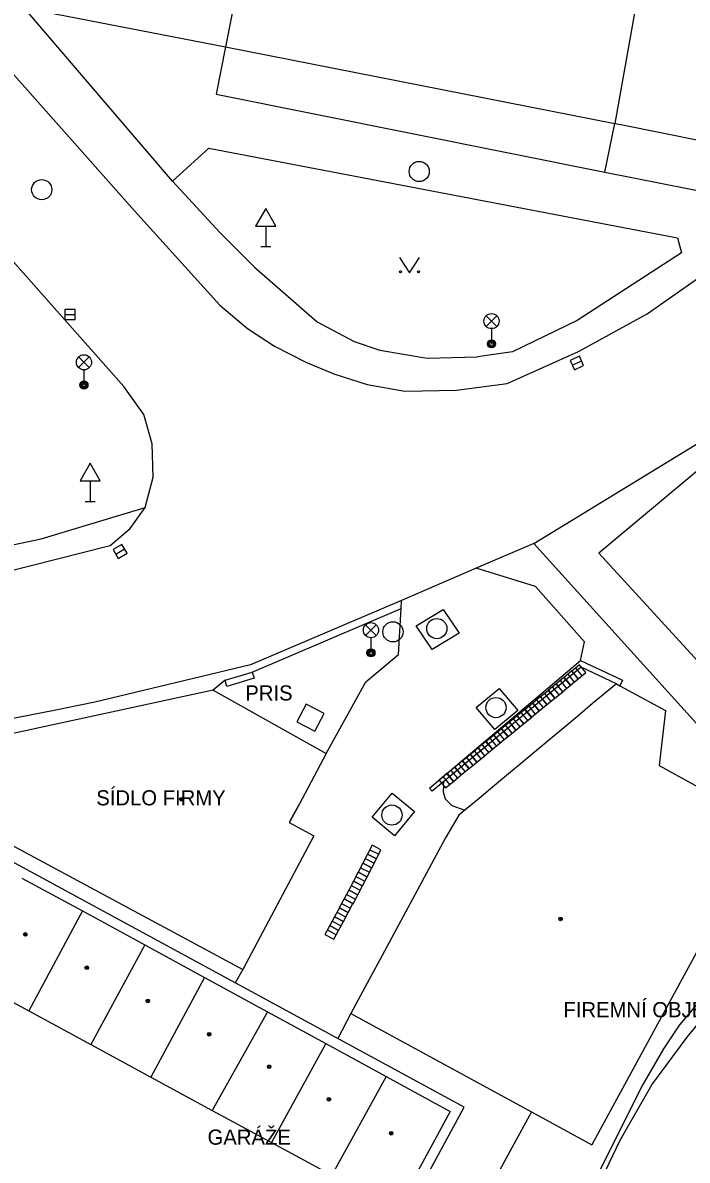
# Model space of a CAD drawing. Extents: x -598233 to -596890, y -1157848 to -1156431.
# Drawn here: x -597063.7 to -597030.8, y -1157692.2 to -1157635.8 of the extents above; entities that cross this region are included whole.
import ezdxf

# ---------------------------------------------------------------- set-up
doc = ezdxf.new("R2010")
doc.units = 0
for name, color, linetype in [('Level 10', 7, 'Continuous'), ('Level 11', 7, 'Continuous'), ('Level 14', 7, 'Continuous'), ('Level 24', 7, 'Continuous'), ('Level 26', 7, 'Continuous'), ('Level 27', 7, 'Continuous'), ('Level 33', 7, 'Continuous'), ('Level 34', 7, 'Continuous'), ('Level 36', 7, 'Continuous'), ('Level 39', 7, 'Continuous'), ('Level 41', 7, 'Continuous'), ('Level 5', 7, 'Continuous'), ('Level 6', 7, 'Continuous'), ('Level 7', 7, 'Continuous')]:
    doc.layers.add(name, color=color, linetype=linetype)

msp = doc.modelspace()

# ---------------------------------------------------------------- linework, layer by layer
at = {"layer": 'Level 10'}
for points in [[(-597149.32, -1157542.42), (-597114.43, -1157581.74), (-597058.19, -1157645.1599), (-597053.96, -1157649.83)], [(-597044.81, -1157654.08), (-597042.24, -1157654.04), (-597039.73, -1157653.71), (-597036.2, -1157652.12), (-597032.81, -1157650.25), (-597030.26, -1157648.4699), (-596998.03, -1157621.12)], [(-597076.44, -1157633.83), (-597058.71, -1157653.85)], [(-597053.96, -1157649.83), (-597052.6, -1157650.98), (-597051.25, -1157651.86), (-597049.71, -1157652.65), (-597048.31, -1157653.23), (-597046.67, -1157653.75), (-597044.81, -1157654.08)], [(-597057.6599, -1157659.84), (-597057.27, -1157658.34), (-597057.32, -1157656.69), (-597057.7199, -1157655.24), (-597058.71, -1157653.85)], [(-597038.4099, -1157661.63), (-597029.25, -1157656.04)], [(-597075.37, -1157664.84), (-597070.49, -1157664.28), (-597067.29, -1157663.73), (-597059.39, -1157661.7199), (-597058.4099, -1157660.89), (-597057.6599, -1157659.84)], [(-597038.41, -1157661.63), (-597041.27, -1157662.85), (-597044.97, -1157664.44), (-597052.45, -1157667.64)], [(-597052.45, -1157667.64), (-597060.15, -1157669.48), (-597062.1599, -1157669.89), (-597066.94, -1157670.81)], [(-597034.14, -1157691.17), (-597032.58, -1157688.43), (-597030.83, -1157686.06), (-597028.79, -1157683.59), (-597026.04, -1157680.94)], [(-597050.02, -1157722.18), (-597035.59, -1157694.21), (-597034.14, -1157691.17)]]:
    msp.add_lwpolyline(points, dxfattribs=at)
at = {"layer": 'Level 11'}
for points in [[(-597063.65, -1157635.1), (-597053.68, -1157637.04)], [(-597056.3, -1157643.68), (-597063.65, -1157635.1)], [(-597053.68, -1157637.04), (-597054.14, -1157639.38), (-597034.9, -1157643.25)], [(-597034.4099, -1157640.83), (-597034.11, -1157640.89), (-597028.05, -1157642.1), (-597022.5, -1157637.28), (-597021.17, -1157638.83)], [(-597034.9, -1157643.25), (-597034.4099, -1157640.83)], [(-597056.3, -1157643.68), (-597054.51, -1157642.06), (-597031.31, -1157646.49), (-597031.11, -1157647.23)], [(-597053.95, -1157646.25), (-597056.3, -1157643.68)], [(-597034.9, -1157643.25), (-597027.89, -1157644.63)], [(-597052.25, -1157647.95), (-597053.95, -1157646.25)], [(-597031.11, -1157647.23), (-597036.27, -1157650.58), (-597039.4699, -1157652.13), (-597041.2, -1157652.38)], [(-597052.25, -1157647.95), (-597049.15, -1157650.65), (-597047.31, -1157651.62), (-597046.04, -1157652.05), (-597043.7, -1157652.45), (-597041.2, -1157652.38)], [(-597029.25, -1157656.04), (-597028.77, -1157656.74), (-597035.2, -1157662.1), (-597021.37, -1157677.18)], [(-597097.96, -1157662.31), (-597091.6599, -1157662.87), (-597088.64, -1157663.06), (-597079.29, -1157663.24), (-597070.69, -1157662.87), (-597068.32, -1157662.55), (-597062.8, -1157661.39), (-597057.6599, -1157659.84)], [(-597036.1, -1157667.42), (-597035.91, -1157666.49), (-597038.33, -1157663.75), (-597041.27, -1157662.85)], [(-597048.7, -1157672.03), (-597046.74, -1157668.47), (-597045.12, -1157667.12), (-597044.99, -1157664.85), (-597044.97, -1157664.44)], [(-597052.36, -1157668), (-597044.99, -1157664.85)], [(-597044.24, -1157665.71), (-597042.9099, -1157664.89), (-597042.12, -1157666.06), (-597043.45, -1157666.88), (-597044.24, -1157665.71)], [(-597043.58, -1157673.74), (-597036.1, -1157667.42)], [(-597036.1, -1157667.42), (-597034.03, -1157668.39)], [(-597036.08, -1157667.75), (-597042.88, -1157673.41), (-597043.45, -1157673.89)], [(-597034.33, -1157668.57), (-597036.08, -1157667.75)], [(-597053.7, -1157668.4), (-597054.29, -1157668.89)], [(-597034.03, -1157668.39), (-597034.15, -1157668.67)], [(-597041.27, -1157669.74), (-597040.13, -1157668.8), (-597039.2, -1157669.89), (-597040.35, -1157670.83), (-597041.27, -1157669.74)], [(-597042.89, -1157673.59), (-597042.9099, -1157673.92)], [(-597042.89, -1157673.59), (-597042.88, -1157673.41)], [(-597045.43, -1157673.98), (-597044.33, -1157674.9), (-597045.31, -1157676.1), (-597046.42, -1157675.18), (-597045.43, -1157673.98)], [(-597043.45, -1157673.89), (-597043.58, -1157673.74)], [(-597042.9099, -1157673.92), (-597042.8, -1157674.27)], [(-597051.69, -1157707.64), (-597041.87, -1157689.53), (-597069.6599, -1157674.45), (-597072.96, -1157680.5), (-597074.59, -1157679.61), (-597075.37, -1157681.09)], [(-597042.8, -1157674.27), (-597042.4699, -1157674.59)], [(-597042.4699, -1157674.59), (-597041.83, -1157674.83)], [(-597052.82, -1157682.72), (-597053.21, -1157683.38)], [(-597047.47, -1157684.89), (-597048.12, -1157686.14)], [(-597031.2, -1157685.46), (-597032, -1157686.64), (-597033.02, -1157688.41), (-597034.54, -1157691.43), (-597038.61, -1157699.61), (-597038.62, -1157699.63), (-597044.68, -1157711.84)]]:
    msp.add_lwpolyline(points, dxfattribs=at)
at = {"layer": 'Level 14'}
for points in [[(-597030.3, -1157684.38), (-597031.2, -1157685.46)], [(-597038.53, -1157689.77), (-597043.51, -1157698.89)]]:
    msp.add_lwpolyline(points, dxfattribs=at)
at = {"layer": 'Level 24'}
msp.add_lwpolyline([(-597053.7, -1157668.4), (-597052.36, -1157668), (-597052.27, -1157668.3), (-597053.61, -1157668.7), (-597053.7, -1157668.4)], dxfattribs=at)
at = {"layer": 'Level 26'}
msp.add_lwpolyline([(-597050.1449, -1157670.4607), (-597049.2592, -1157670.925), (-597048.7949, -1157670.0393), (-597049.6806, -1157669.575)], close=True, dxfattribs=at)
at = {"layer": 'Level 27'}
for p, q in [((-597061.63, -1157650.29), (-597061.13, -1157650.29)), ((-597036.5079, -1157652.7928), (-597036.0521, -1157652.5872)), ((-597059.1159, -1157662.146), (-597058.6841, -1157661.894)), ((-597036.3484, -1157667.7866), (-597036.0316, -1157668.1734)), ((-597037.1184, -1157668.4166), (-597036.8016, -1157668.8034)), ((-597036.7284, -1157668.0966), (-597036.4116, -1157668.4834)), ((-597037.8884, -1157669.0566), (-597037.5716, -1157669.4434)), ((-597037.4984, -1157668.7366), (-597037.1816, -1157669.1234)), ((-597038.6584, -1157669.6866), (-597038.3416, -1157670.0734)), ((-597038.2784, -1157669.3666), (-597037.9616, -1157669.7534)), ((-597039.0484, -1157670.0066), (-597038.7316, -1157670.3934)), ((-597039.8183, -1157670.6366), (-597039.5015, -1157671.0234)), ((-597039.4284, -1157670.3166), (-597039.1116, -1157670.7034)), ((-597040.5884, -1157671.2666), (-597040.2716, -1157671.6534)), ((-597040.2084, -1157670.9566), (-597039.8916, -1157671.3434)), ((-597041.3584, -1157671.9066), (-597041.0416, -1157672.2934)), ((-597040.9784, -1157671.5866), (-597040.6616, -1157671.9734)), ((-597041.7484, -1157672.2266), (-597041.4316, -1157672.6134)), ((-597042.5184, -1157672.8566), (-597042.2016, -1157673.2434)), ((-597042.1384, -1157672.5366), (-597041.8216, -1157672.9234)), ((-597042.9084, -1157673.1766), (-597042.5916, -1157673.5634)), ((-597046.5423, -1157676.7856), (-597046.0977, -1157677.0144)), ((-597046.7723, -1157677.2256), (-597046.3277, -1157677.4544)), ((-597047.2321, -1157678.1152), (-597046.7879, -1157678.3448)), ((-597047.0023, -1157677.6756), (-597046.5577, -1157677.9044)), ((-597047.4613, -1157678.5637), (-597047.0187, -1157678.7963)), ((-597047.691, -1157679.0034), (-597047.2488, -1157679.2366)), ((-597047.9306, -1157679.4424), (-597047.4894, -1157679.6776)), ((-597048.3999, -1157680.3211), (-597047.9601, -1157680.5589)), ((-597048.1602, -1157679.8817), (-597047.7198, -1157680.1183)), ((-597048.6389, -1157680.7592), (-597048.2011, -1157681.0008))]:
    msp.add_line(p, q, dxfattribs=at)
for points in [[(-597061.63, -1157650.54), (-597061.13, -1157650.54), (-597061.13, -1157650.04), (-597061.63, -1157650.04)], [(-597036.4051, -1157653.0207), (-597035.9493, -1157652.8151), (-597036.1549, -1157652.3593), (-597036.6107, -1157652.5649)], [(-597058.9899, -1157662.3619), (-597058.5581, -1157662.1099), (-597058.8101, -1157661.6781), (-597059.2419, -1157661.9301)], [(-597036.9218, -1157668.2551), (-597036.6049, -1157668.6418), (-597036.2182, -1157668.3249), (-597036.5351, -1157667.9382)], [(-597036.5418, -1157667.9451), (-597036.2249, -1157668.3318), (-597035.8382, -1157668.0149), (-597036.1551, -1157667.6282)], [(-597037.6918, -1157668.8951), (-597037.3749, -1157669.2818), (-597036.9882, -1157668.9649), (-597037.3051, -1157668.5782)], [(-597037.3118, -1157668.5751), (-597036.9949, -1157668.9618), (-597036.6082, -1157668.6449), (-597036.9251, -1157668.2582)], [(-597038.0818, -1157669.2151), (-597037.7649, -1157669.6018), (-597037.3782, -1157669.2849), (-597037.6951, -1157668.8982)], [(-597038.8518, -1157669.8451), (-597038.5349, -1157670.2318), (-597038.1482, -1157669.9149), (-597038.4651, -1157669.5282)], [(-597038.4718, -1157669.5251), (-597038.1549, -1157669.9118), (-597037.7682, -1157669.5949), (-597038.0851, -1157669.2082)], [(-597039.6218, -1157670.4751), (-597039.3049, -1157670.8618), (-597038.9182, -1157670.5449), (-597039.2351, -1157670.1582)], [(-597039.2418, -1157670.1651), (-597038.9249, -1157670.5518), (-597038.5382, -1157670.2349), (-597038.8551, -1157669.8482)], [(-597040.4018, -1157671.1151), (-597040.0849, -1157671.5018), (-597039.6982, -1157671.1849), (-597040.0151, -1157670.7982)], [(-597040.0117, -1157670.7951), (-597039.6948, -1157671.1818), (-597039.3081, -1157670.8649), (-597039.625, -1157670.4782)], [(-597040.7818, -1157671.4251), (-597040.4649, -1157671.8118), (-597040.0782, -1157671.4949), (-597040.3951, -1157671.1082)], [(-597041.5518, -1157672.0651), (-597041.2349, -1157672.4518), (-597040.8482, -1157672.1349), (-597041.1651, -1157671.7482)], [(-597041.1718, -1157671.7451), (-597040.8549, -1157672.1318), (-597040.4682, -1157671.8149), (-597040.7851, -1157671.4282)], [(-597042.3318, -1157672.6951), (-597042.0149, -1157673.0818), (-597041.6282, -1157672.7649), (-597041.9451, -1157672.3782)], [(-597041.9418, -1157672.3851), (-597041.6249, -1157672.7718), (-597041.2382, -1157672.4549), (-597041.5551, -1157672.0682)], [(-597043.1018, -1157673.3351), (-597042.7849, -1157673.7218), (-597042.3982, -1157673.4049), (-597042.7151, -1157673.0182)], [(-597042.7118, -1157673.0151), (-597042.3949, -1157673.4018), (-597042.0082, -1157673.0849), (-597042.3251, -1157672.6982)], [(-597046.8867, -1157677.448), (-597046.442, -1157677.6767), (-597046.2133, -1157677.232), (-597046.658, -1157677.0033)], [(-597046.6567, -1157677.008), (-597046.212, -1157677.2367), (-597045.9833, -1157676.792), (-597046.428, -1157676.5633)], [(-597047.1167, -1157677.898), (-597046.672, -1157678.1267), (-597046.4433, -1157677.682), (-597046.888, -1157677.4533)], [(-597047.3469, -1157678.3373), (-597046.9027, -1157678.5669), (-597046.6731, -1157678.1227), (-597047.1173, -1157677.8931)], [(-597047.5776, -1157678.785), (-597047.135, -1157679.0176), (-597046.9024, -1157678.575), (-597047.345, -1157678.3424)], [(-597048.0482, -1157679.6631), (-597047.6069, -1157679.8982), (-597047.3718, -1157679.4569), (-597047.8131, -1157679.2218)], [(-597047.8077, -1157679.2245), (-597047.3654, -1157679.4578), (-597047.1321, -1157679.0155), (-597047.5744, -1157678.7822)], [(-597048.2785, -1157680.102), (-597047.838, -1157680.3385), (-597047.6015, -1157679.898), (-597048.042, -1157679.6615)], [(-597048.5188, -1157680.5411), (-597048.0789, -1157680.7788), (-597047.8412, -1157680.3389), (-597048.2811, -1157680.1012)], [(-597048.7597, -1157680.9781), (-597048.3219, -1157681.2197), (-597048.0803, -1157680.7819), (-597048.5181, -1157680.5403)]]:
    msp.add_lwpolyline(points, close=True, dxfattribs=at)
for centre in [(-597044.09, -1157643.21), (-597062.78, -1157644.11), (-597045.39, -1157666), (-597043.2199, -1157665.84), (-597040.29, -1157669.75), (-597045.44, -1157675.07)]:
    msp.add_circle(centre, 0.5, dxfattribs=at)
at = {"layer": 'Level 33'}
for p, q in [((-597040.775, -1157650.88), (-597040.245, -1157650.35)), ((-597040.775, -1157650.35), (-597040.245, -1157650.88)), ((-597040.51, -1157650.99), (-597040.51, -1157651.74)), ((-597060.955, -1157652.92), (-597060.425, -1157652.39)), ((-597060.955, -1157652.39), (-597060.425, -1157652.92)), ((-597060.69, -1157653.03), (-597060.69, -1157653.78)), ((-597046.745, -1157666.18), (-597046.215, -1157665.65)), ((-597046.745, -1157665.65), (-597046.215, -1157666.18)), ((-597046.48, -1157666.29), (-597046.48, -1157667.04))]:
    msp.add_line(p, q, dxfattribs=at)
for centre, radius in [((-597040.51, -1157650.615), 0.375), ((-597040.51, -1157651.74), 0.2), ((-597040.51, -1157651.74), 0.1445), ((-597040.51, -1157651.74), 0.0876), ((-597060.69, -1157652.655), 0.375), ((-597060.69, -1157653.78), 0.2), ((-597060.69, -1157653.78), 0.1445), ((-597060.69, -1157653.78), 0.0876), ((-597046.48, -1157665.915), 0.375), ((-597046.48, -1157667.04), 0.2), ((-597046.48, -1157667.04), 0.1445), ((-597046.48, -1157667.04), 0.0876)]:
    msp.add_circle(centre, radius, dxfattribs=at)
at = {"layer": 'Level 34'}
for p, q in [((-597051.69, -1157645.912), (-597051.69, -1157646.93)), ((-597051.94, -1157646.93), (-597051.44, -1157646.93)), ((-597060.38, -1157658.522), (-597060.38, -1157659.54)), ((-597060.63, -1157659.54), (-597060.13, -1157659.54))]:
    msp.add_line(p, q, dxfattribs=at)
for points in [[(-597052.19, -1157645.912), (-597051.19, -1157645.912), (-597051.69, -1157645.046)], [(-597060.88, -1157658.522), (-597059.88, -1157658.522), (-597060.38, -1157657.656)]]:
    msp.add_lwpolyline(points, close=True, dxfattribs=at)
at = {"layer": 'Level 36'}
msp.add_lwpolyline([(-597045.07, -1157647.4699), (-597044.57, -1157648.2199), (-597044.07, -1157647.4699)], dxfattribs=at)
for centre in [(-597045.0202, -1157648.1697), (-597044.1208, -1157648.1697)]:
    msp.add_circle(centre, 0.05, dxfattribs=at)
at = {"layer": 'Level 39'}
for centre, radius in [((-597055.87, -1157674.29), 0.09), ((-597055.87, -1157674.29), 0.0398), ((-597037.09, -1157680.21), 0.09), ((-597037.09, -1157680.21), 0.0398), ((-597063.59, -1157680.98), 0.09), ((-597063.59, -1157680.98), 0.0398), ((-597060.55, -1157682.63), 0.09), ((-597060.55, -1157682.63), 0.0398), ((-597057.53, -1157684.27), 0.09), ((-597057.53, -1157684.27), 0.0398), ((-597054.49, -1157685.92), 0.09), ((-597054.49, -1157685.92), 0.0398), ((-597051.52, -1157687.53), 0.09), ((-597051.52, -1157687.53), 0.0398), ((-597048.56, -1157689.14), 0.09), ((-597048.56, -1157689.14), 0.0398), ((-597045.48, -1157690.82), 0.09), ((-597045.48, -1157690.82), 0.0398)]:
    msp.add_circle(centre, radius, dxfattribs=at)
at = {"layer": 'Level 5'}
for points in [[(-597051.29, -1157624.92), (-597053.68, -1157637.04)], [(-597032.25, -1157628.67), (-597034.4099, -1157640.83)], [(-597053.68, -1157637.04), (-597034.4099, -1157640.83)], [(-597034.33, -1157668.57), (-597035.51, -1157669.55)], [(-597034.33, -1157668.57), (-597034.15, -1157668.67)], [(-597054.29, -1157668.89), (-597067.49, -1157671.74)], [(-597054.29, -1157668.89), (-597048.7, -1157672.03)], [(-597034.15, -1157668.67), (-597031.9, -1157669.89)], [(-597035.51, -1157669.55), (-597036.24, -1157670.17)], [(-597036.24, -1157670.17), (-597040.36, -1157673.6)], [(-597031.9, -1157669.89), (-597032.21, -1157672.61)], [(-597048.7, -1157672.03), (-597050.04, -1157674.54)], [(-597032.21, -1157672.61), (-597026.92, -1157675.53)], [(-597040.36, -1157673.6), (-597041.13, -1157674.25)], [(-597068.79, -1157674.13), (-597052.82, -1157682.7199)], [(-597050.04, -1157674.54), (-597050.48, -1157675.35)], [(-597041.13, -1157674.25), (-597041.83, -1157674.83)], [(-597042.13, -1157675.08), (-597042.79, -1157676.2)], [(-597041.83, -1157674.83), (-597042.13, -1157675.08)], [(-597050.48, -1157675.35), (-597050.53, -1157675.44)], [(-597050.53, -1157675.44), (-597049.31, -1157676.1)], [(-597026.92, -1157675.53), (-597035.54, -1157691.4)], [(-597049.31, -1157676.1), (-597052.82, -1157682.7199)], [(-597042.79, -1157676.2), (-597043.37, -1157677.27)], [(-597043.37, -1157677.27), (-597043.73, -1157677.95)], [(-597043.73, -1157677.95), (-597046.1599, -1157682.45)], [(-597063.76, -1157678.19), (-597060.76, -1157679.82)], [(-597060.76, -1157679.82), (-597063.42, -1157684.77)], [(-597060.76, -1157679.82), (-597057.68, -1157681.5)], [(-597057.68, -1157681.5), (-597060.35, -1157686.43)], [(-597057.68, -1157681.5), (-597054.7199, -1157683.11)], [(-597046.1599, -1157682.45), (-597046.34, -1157682.78)], [(-597066.43, -1157683.14), (-597063.42, -1157684.77)], [(-597054.7199, -1157683.11), (-597057.38, -1157688.04)], [(-597054.7199, -1157683.11), (-597051.6, -1157684.81)], [(-597046.34, -1157682.78), (-597047.23, -1157684.44)], [(-597063.42, -1157684.77), (-597060.35, -1157686.43)], [(-597051.6, -1157684.81), (-597054.34, -1157689.69)], [(-597051.6, -1157684.81), (-597048.7199, -1157686.38)], [(-597047.23, -1157684.44), (-597047.4699, -1157684.89)], [(-597047.4699, -1157684.89), (-597038.53, -1157689.77)], [(-597060.35, -1157686.43), (-597057.38, -1157688.04)], [(-597048.7199, -1157686.38), (-597051.4, -1157691.28)], [(-597048.7199, -1157686.38), (-597045.7199, -1157688.01)], [(-597057.38, -1157688.04), (-597054.34, -1157689.69)], [(-597045.7199, -1157688.01), (-597048.42, -1157692.9)], [(-597045.7199, -1157688.01), (-597042.55, -1157689.74)], [(-597054.34, -1157689.69), (-597051.4, -1157691.28)], [(-597042.55, -1157689.74), (-597045.21, -1157694.64)], [(-597038.53, -1157689.77), (-597035.54, -1157691.4)], [(-597051.4, -1157691.28), (-597048.42, -1157692.9)]]:
    msp.add_lwpolyline(points, dxfattribs=at)
at = {"layer": 'Level 6'}
for points in [[(-597035.51, -1157669.55), (-597036.24, -1157670.17)], [(-597040.36, -1157673.6), (-597041.13, -1157674.25)], [(-597050.48, -1157675.35), (-597050.04, -1157674.54)], [(-597042.79, -1157676.2), (-597043.37, -1157677.27)], [(-597043.73, -1157677.95), (-597046.1599, -1157682.45)], [(-597046.34, -1157682.78), (-597047.23, -1157684.44)]]:
    msp.add_lwpolyline(points, dxfattribs=at)
at = {"layer": 'Level 7'}
msp.add_lwpolyline([(-597038.4099, -1157661.63), (-597026.34, -1157675)], dxfattribs=at)

# ---------------------------------------------------------------- texts
at = {"layer": 'Level 41'}
for s, p in [('PRIS', (-597052.7, -1157669.4)), ('SÍDLO FIRMY', (-597060.08, -1157674.59)), ('FIREMNÍ OBJEKT', (-597036.95, -1157685.08)), ('GARÁŽE', (-597054.57, -1157691.39))]:
    msp.add_text(s, height=0.75, dxfattribs=at).set_placement(p)

doc.saveas('drawing.dxf')
